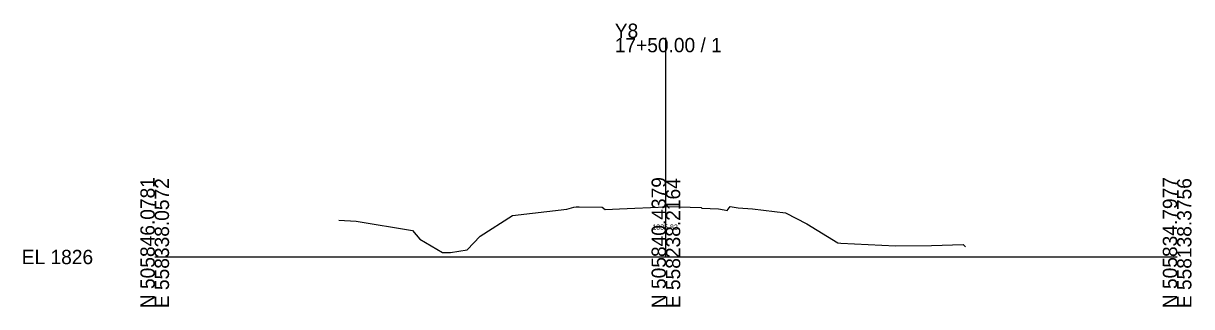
# Model space of a CAD drawing. Extents: x -26 to 203, y -10 to 8070.
# Drawn here: x -25.7 to 202.8, y 7490.3 to 7545.6 of the extents above; entities that cross this region are included whole.
import ezdxf

# ---------------------------------------------------------------- set-up
doc = ezdxf.new("R2010")
doc.units = 0
for name, color, linetype in [('Default', 7, 'Continuous'), ('Exist Cross Section Cell', 7, 'Continuous'), ('Exist XS Center Line Elevation Label', 7, 'Continuous'), ('Exist XS Ground Line', 7, 'Continuous')]:
    doc.layers.add(name, color=color, linetype=linetype)

msp = doc.modelspace()

# ---------------------------------------------------------------- linework, layer by layer
at = {"layer": 'Exist Cross Section Cell'}
for p, q in [((100, 7500), (100, 7542.8)), ((0, 7500), (100, 7500)), ((100, 7500), (200, 7500))]:
    msp.add_line(p, q, dxfattribs=at)
at = {"layer": 'Exist XS Ground Line'}
for p, q in [((80.59, 7509.36), (81.98, 7509.73)), ((81.98, 7509.73), (82.43, 7509.82)), ((82.43, 7509.82), (83.03, 7509.81)), ((83.03, 7509.81), (87.5, 7509.71)), ((87.5, 7509.71), (88.12, 7509.3)), ((90.91, 7509.4), (100, 7509.82)), ((100, 7509.82), (100.44, 7509.84)), ((100.44, 7509.84), (106.87, 7509.65)), ((106.87, 7509.65), (107.03, 7509.53)), ((111.99, 7509.11), (112.55, 7509.84)), ((112.55, 7509.84), (114.15, 7509.63)), ((114.15, 7509.63), (116.93, 7509.39)), ((63.66, 7504.06), (69.96, 7508.13)), ((69.96, 7508.13), (80.59, 7509.36)), ((88.12, 7509.3), (89.53, 7509.35)), ((89.53, 7509.35), (90.91, 7509.4)), ((107.03, 7509.53), (110.27, 7509.4)), ((110.27, 7509.4), (111.41, 7509.21)), ((111.41, 7509.21), (111.99, 7509.11)), ((116.93, 7509.39), (123.38, 7508.61)), ((123.38, 7508.61), (127.57, 7506.49)), ((36.04, 7507.21), (39.38, 7506.97)), ((39.38, 7506.97), (50.41, 7505.16)), ((50.41, 7505.16), (51.89, 7503.48)), ((127.57, 7506.49), (133.61, 7502.77)), ((51.89, 7503.48), (56.28, 7500.86)), ((61.11, 7501.4), (63.66, 7504.06)), ((133.61, 7502.77), (134.2, 7502.67)), ((56.28, 7500.86), (57.88, 7500.86)), ((57.88, 7500.86), (61.11, 7501.4)), ((134.2, 7502.67), (144.88, 7502.17)), ((144.88, 7502.17), (151.96, 7502.22)), ((151.96, 7502.22), (158.16, 7502.47)), ((158.16, 7502.47), (158.61, 7501.98))]:
    msp.add_line(p, q, dxfattribs=at)

# ---------------------------------------------------------------- texts
at = {"layer": 'Default'}
msp.add_text('-', height=0.0001, dxfattribs=at).set_placement((0, 7500))
at = {"layer": 'Exist Cross Section Cell'}
for s, p in [('Y8', (90, 7542.8)), ('17+50.00 / 1', (90, 7540)), ('EL 1826', (-26, 7498.6))]:
    msp.add_text(s, height=2.8, dxfattribs=at).set_placement(p)
for s, p in [('N 505846.0781', (0, 7490)), ('E 558338.0572', (2.8, 7490)), ('N 505840.4379', (100, 7490)), ('E 558238.2164', (102.8, 7490)), ('N 505834.7977', (200, 7490)), ('E 558138.3756', (202.8, 7490))]:
    msp.add_text(s, height=2.8, rotation=90, dxfattribs=at).set_placement(p)
at = {"layer": 'Exist XS Center Line Elevation Label'}
msp.add_text('1835.82', height=1, dxfattribs=at).set_placement((97.34, 7505.35))

doc.saveas('drawing.dxf')
